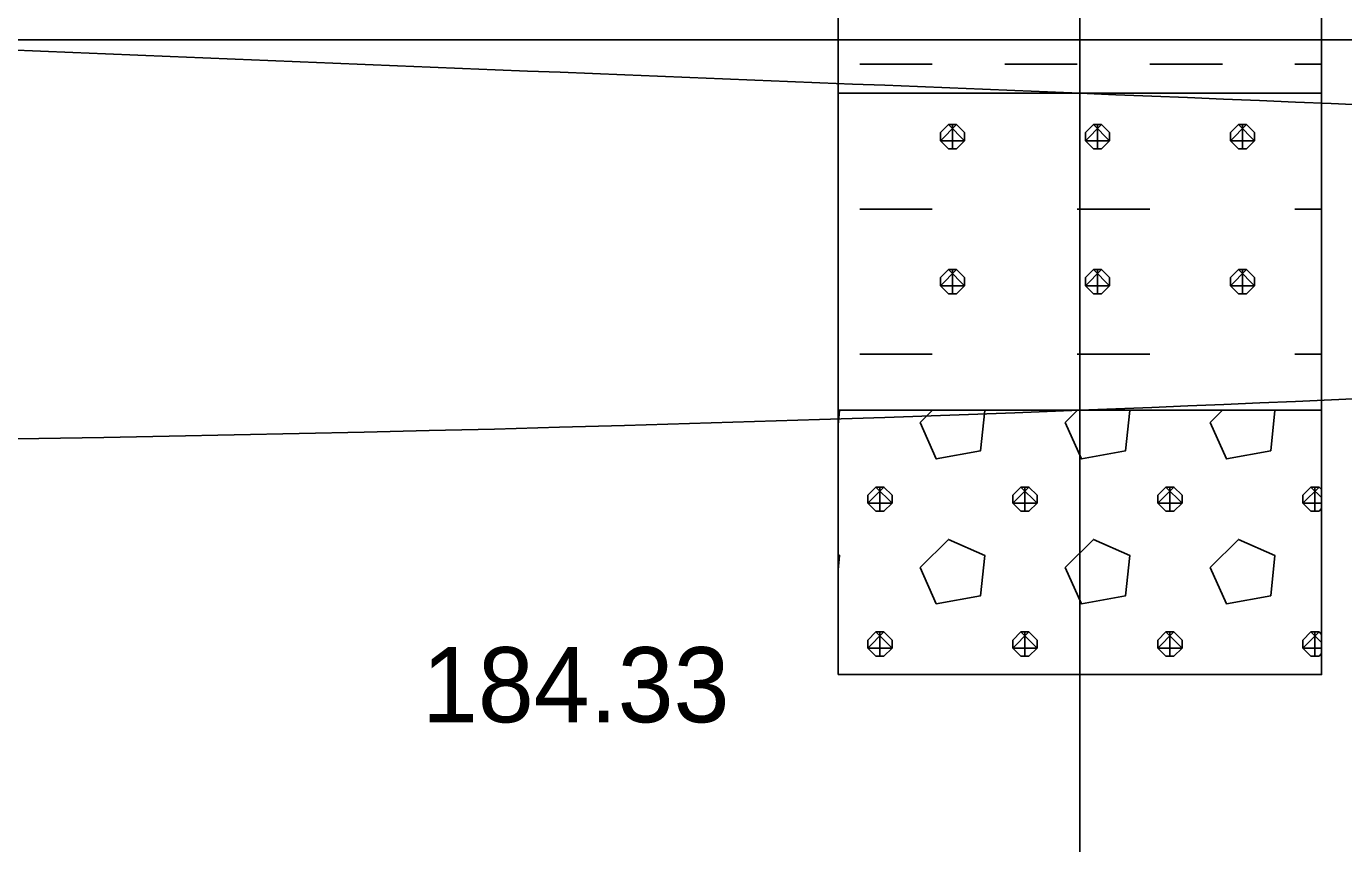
# Model space of a CAD drawing. Extents: x 3042 to 4120, y 576 to 2694.
# Drawn here: x 3421.37 to 3433.83, y 879.91 to 887.64 of the extents above; entities that cross this region are included whole.
import ezdxf

# ---------------------------------------------------------------- set-up
doc = ezdxf.new("R2010")
doc.units = 0
for name, color, linetype in [('17', 7, 'Continuous'), ('18', 7, 'Continuous'), ('51', 7, 'Continuous'), ('53', 7, 'Continuous'), ('56', 7, 'Continuous'), ('pomocna', 7, 'Continuous'), ('rozhraní', 7, 'Continuous')]:
    doc.layers.add(name, color=color, linetype=linetype)

msp = doc.modelspace()

# ---------------------------------------------------------------- linework, layer by layer
at = {"layer": '18'}
for p, q in [((3431.3317167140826, 869.8590620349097), (3431.3317167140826, 916.5090620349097)), ((3431.3317167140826, 881.8900620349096), (3431.3317167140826, 881.1280620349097)), ((3430.950716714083, 881.5090620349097), (3431.712716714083, 881.5090620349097))]:
    msp.add_line(p, q, dxfattribs=at)
at = {"layer": '51'}
for points in [[(3429.045716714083, 887.0090620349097), (3433.6177167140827, 887.0090620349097), (3433.6177167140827, 901.5090620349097), (3429.045716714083, 901.5090620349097)], [(3429.045716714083, 884.0090620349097), (3433.6177167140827, 884.0090620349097), (3433.6177167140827, 887.0090620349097), (3429.045716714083, 887.0090620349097)], [(3429.045716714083, 881.5090620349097), (3433.6177167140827, 881.5090620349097), (3433.6177167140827, 884.0090620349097), (3429.045716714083, 884.0090620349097)]]:
    msp.add_lwpolyline(points, close=True, dxfattribs=at)
for points in [[(3429.2499167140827, 887.2835620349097), (3429.935716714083, 887.2835620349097)], [(3430.6215167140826, 887.2835620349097), (3431.307316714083, 887.2835620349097)], [(3431.993116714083, 887.2835620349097), (3432.678916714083, 887.2835620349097)], [(3433.364716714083, 887.2835620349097), (3433.6177167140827, 887.2835620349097)], [(3430.088116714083, 886.7120620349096), (3430.011916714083, 886.6358620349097), (3430.011916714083, 886.5596620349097), (3430.088116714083, 886.4834620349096), (3430.164316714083, 886.4834620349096), (3430.240516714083, 886.5596620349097), (3430.240516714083, 886.6358620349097), (3430.164316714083, 886.7120620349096), (3430.088116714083, 886.7120620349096), (3430.240516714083, 886.5596620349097), (3430.011916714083, 886.5596620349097), (3430.164316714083, 886.7120620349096)], [(3430.1262167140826, 886.4834620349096), (3430.1262167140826, 886.7120620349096)], [(3431.459716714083, 886.7120620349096), (3431.383516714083, 886.6358620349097), (3431.383516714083, 886.5596620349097), (3431.459716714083, 886.4834620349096), (3431.5359167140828, 886.4834620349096), (3431.6121167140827, 886.5596620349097), (3431.6121167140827, 886.6358620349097), (3431.5359167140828, 886.7120620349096), (3431.459716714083, 886.7120620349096), (3431.6121167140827, 886.5596620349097), (3431.383516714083, 886.5596620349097), (3431.5359167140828, 886.7120620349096)], [(3431.497816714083, 886.4834620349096), (3431.497816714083, 886.7120620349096)], [(3432.8313167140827, 886.7120620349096), (3432.7551167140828, 886.6358620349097), (3432.7551167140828, 886.5596620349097), (3432.8313167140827, 886.4834620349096), (3432.9075167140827, 886.4834620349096), (3432.9837167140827, 886.5596620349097), (3432.9837167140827, 886.6358620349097), (3432.9075167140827, 886.7120620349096), (3432.8313167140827, 886.7120620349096), (3432.9837167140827, 886.5596620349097), (3432.7551167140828, 886.5596620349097), (3432.9075167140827, 886.7120620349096)], [(3432.869416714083, 886.4834620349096), (3432.869416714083, 886.7120620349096)], [(3429.2499167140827, 885.9119620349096), (3429.935716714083, 885.9119620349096)], [(3431.307316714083, 885.9119620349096), (3431.993116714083, 885.9119620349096)], [(3433.364716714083, 885.9119620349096), (3433.6177167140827, 885.9119620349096)], [(3430.088116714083, 885.3404620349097), (3430.011916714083, 885.2642620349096), (3430.011916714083, 885.1880620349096), (3430.088116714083, 885.1118620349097), (3430.164316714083, 885.1118620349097), (3430.240516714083, 885.1880620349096), (3430.240516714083, 885.2642620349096), (3430.164316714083, 885.3404620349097), (3430.088116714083, 885.3404620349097), (3430.240516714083, 885.1880620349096), (3430.011916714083, 885.1880620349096), (3430.164316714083, 885.3404620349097)], [(3430.1262167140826, 885.1118620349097), (3430.1262167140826, 885.3404620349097)], [(3431.459716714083, 885.3404620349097), (3431.383516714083, 885.2642620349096), (3431.383516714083, 885.1880620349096), (3431.459716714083, 885.1118620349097), (3431.5359167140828, 885.1118620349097), (3431.6121167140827, 885.1880620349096), (3431.6121167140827, 885.2642620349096), (3431.5359167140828, 885.3404620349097), (3431.459716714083, 885.3404620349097), (3431.6121167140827, 885.1880620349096), (3431.383516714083, 885.1880620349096), (3431.5359167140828, 885.3404620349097)], [(3431.497816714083, 885.1118620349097), (3431.497816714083, 885.3404620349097)], [(3432.8313167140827, 885.3404620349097), (3432.7551167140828, 885.2642620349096), (3432.7551167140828, 885.1880620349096), (3432.8313167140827, 885.1118620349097), (3432.9075167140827, 885.1118620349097), (3432.9837167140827, 885.1880620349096), (3432.9837167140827, 885.2642620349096), (3432.9075167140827, 885.3404620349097), (3432.8313167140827, 885.3404620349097), (3432.9837167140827, 885.1880620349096), (3432.7551167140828, 885.1880620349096), (3432.9075167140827, 885.3404620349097)], [(3432.869416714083, 885.1118620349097), (3432.869416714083, 885.3404620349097)], [(3429.2499167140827, 884.5403620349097), (3429.935716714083, 884.5403620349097)], [(3431.307316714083, 884.5403620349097), (3431.993116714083, 884.5403620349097)], [(3433.364716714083, 884.5403620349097), (3433.6177167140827, 884.5403620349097)], [(3429.045716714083, 883.8699620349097), (3429.059416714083, 884.0069620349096), (3429.054666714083, 884.0090620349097)], [(3429.8214167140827, 883.8926620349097), (3429.9738167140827, 883.5497620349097), (3430.3929167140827, 883.6259620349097), (3430.431016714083, 884.0069620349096), (3430.426266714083, 884.0090620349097)], [(3429.9378167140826, 884.0090620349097), (3429.8214167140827, 883.8926620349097)], [(3431.1930167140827, 883.8926620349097), (3431.3454167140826, 883.5497620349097), (3431.7645167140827, 883.6259620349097), (3431.802616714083, 884.0069620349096), (3431.797866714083, 884.0090620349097)], [(3431.309416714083, 884.0090620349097), (3431.1930167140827, 883.8926620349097)], [(3432.5646167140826, 883.8926620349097), (3432.717016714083, 883.5497620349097), (3433.1361167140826, 883.6259620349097), (3433.174216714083, 884.0069620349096), (3433.169466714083, 884.0090620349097)], [(3432.681016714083, 884.0090620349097), (3432.5646167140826, 883.8926620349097)], [(3429.4023167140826, 883.2830620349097), (3429.3261167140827, 883.2068620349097), (3429.3261167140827, 883.1306620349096), (3429.4023167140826, 883.0544620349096), (3429.4785167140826, 883.0544620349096), (3429.554716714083, 883.1306620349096), (3429.554716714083, 883.2068620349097), (3429.4785167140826, 883.2830620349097), (3429.4023167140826, 883.2830620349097), (3429.554716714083, 883.1306620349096), (3429.3261167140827, 883.1306620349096), (3429.4785167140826, 883.2830620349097)], [(3429.440416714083, 883.0544620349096), (3429.440416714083, 883.2830620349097)], [(3430.773916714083, 883.2830620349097), (3430.6977167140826, 883.2068620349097), (3430.6977167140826, 883.1306620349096), (3430.773916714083, 883.0544620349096), (3430.850116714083, 883.0544620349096), (3430.926316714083, 883.1306620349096), (3430.926316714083, 883.2068620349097), (3430.850116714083, 883.2830620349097), (3430.773916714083, 883.2830620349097), (3430.926316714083, 883.1306620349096), (3430.6977167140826, 883.1306620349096), (3430.850116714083, 883.2830620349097)], [(3430.812016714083, 883.0544620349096), (3430.812016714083, 883.2830620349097)], [(3432.145516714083, 883.2830620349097), (3432.069316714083, 883.2068620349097), (3432.069316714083, 883.1306620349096), (3432.145516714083, 883.0544620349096), (3432.221716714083, 883.0544620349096), (3432.297916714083, 883.1306620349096), (3432.297916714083, 883.2068620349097), (3432.221716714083, 883.2830620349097), (3432.145516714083, 883.2830620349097), (3432.297916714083, 883.1306620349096), (3432.069316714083, 883.1306620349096), (3432.221716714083, 883.2830620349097)], [(3432.1836167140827, 883.0544620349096), (3432.1836167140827, 883.2830620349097)], [(3433.517116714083, 883.2830620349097), (3433.440916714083, 883.2068620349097), (3433.440916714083, 883.1306620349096), (3433.517116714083, 883.0544620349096), (3433.593316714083, 883.0544620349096), (3433.6177167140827, 883.0788620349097)], [(3433.6177167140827, 883.1306620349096), (3433.440916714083, 883.1306620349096), (3433.593316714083, 883.2830620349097)], [(3433.6177167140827, 883.2586620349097), (3433.593316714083, 883.2830620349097), (3433.517116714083, 883.2830620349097), (3433.6177167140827, 883.1824620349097)], [(3433.5552167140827, 883.0544620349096), (3433.5552167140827, 883.2830620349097)], [(3429.8214167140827, 882.5210620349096), (3429.9738167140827, 882.1781620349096), (3430.3929167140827, 882.2543620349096), (3430.431016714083, 882.6353620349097), (3430.088116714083, 882.7877620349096), (3429.8214167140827, 882.5210620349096)], [(3431.1930167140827, 882.5210620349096), (3431.3454167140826, 882.1781620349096), (3431.7645167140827, 882.2543620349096), (3431.802616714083, 882.6353620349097), (3431.459716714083, 882.7877620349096), (3431.1930167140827, 882.5210620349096)], [(3432.5646167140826, 882.5210620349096), (3432.717016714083, 882.1781620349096), (3433.1361167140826, 882.2543620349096), (3433.174216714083, 882.6353620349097), (3432.8313167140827, 882.7877620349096), (3432.5646167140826, 882.5210620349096)], [(3429.045716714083, 882.4983620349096), (3429.059416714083, 882.6353620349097), (3429.045716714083, 882.6414620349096)], [(3429.4023167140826, 881.9114620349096), (3429.3261167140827, 881.8352620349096), (3429.3261167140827, 881.7590620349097), (3429.4023167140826, 881.6828620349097), (3429.4785167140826, 881.6828620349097), (3429.554716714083, 881.7590620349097), (3429.554716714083, 881.8352620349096), (3429.4785167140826, 881.9114620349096), (3429.4023167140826, 881.9114620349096), (3429.554716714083, 881.7590620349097), (3429.3261167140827, 881.7590620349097), (3429.4785167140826, 881.9114620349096)], [(3429.440416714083, 881.6828620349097), (3429.440416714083, 881.9114620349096)], [(3430.773916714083, 881.9114620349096), (3430.6977167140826, 881.8352620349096), (3430.6977167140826, 881.7590620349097), (3430.773916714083, 881.6828620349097), (3430.850116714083, 881.6828620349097), (3430.926316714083, 881.7590620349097), (3430.926316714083, 881.8352620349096), (3430.850116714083, 881.9114620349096), (3430.773916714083, 881.9114620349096), (3430.926316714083, 881.7590620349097), (3430.6977167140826, 881.7590620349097), (3430.850116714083, 881.9114620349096)], [(3430.812016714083, 881.6828620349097), (3430.812016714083, 881.9114620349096)], [(3432.145516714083, 881.9114620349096), (3432.069316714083, 881.8352620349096), (3432.069316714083, 881.7590620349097), (3432.145516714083, 881.6828620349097), (3432.221716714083, 881.6828620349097), (3432.297916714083, 881.7590620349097), (3432.297916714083, 881.8352620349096), (3432.221716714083, 881.9114620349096), (3432.145516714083, 881.9114620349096), (3432.297916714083, 881.7590620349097), (3432.069316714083, 881.7590620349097), (3432.221716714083, 881.9114620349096)], [(3432.1836167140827, 881.6828620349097), (3432.1836167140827, 881.9114620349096)], [(3433.517116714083, 881.9114620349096), (3433.440916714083, 881.8352620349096), (3433.440916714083, 881.7590620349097), (3433.517116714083, 881.6828620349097), (3433.593316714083, 881.6828620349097), (3433.6177167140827, 881.7072620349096)], [(3433.6177167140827, 881.7590620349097), (3433.440916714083, 881.7590620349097), (3433.593316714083, 881.9114620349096)], [(3433.6177167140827, 881.8870620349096), (3433.593316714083, 881.9114620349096), (3433.517116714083, 881.9114620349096), (3433.6177167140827, 881.8108620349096)], [(3433.5552167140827, 881.6828620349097), (3433.5552167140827, 881.9114620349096)]]:
    msp.add_lwpolyline(points, dxfattribs=at)
at = {"layer": '53'}
for points in [[(3429.045716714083, 916.5090620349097), (3429.045716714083, 881.5090620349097)], [(3433.6177167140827, 916.5090620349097), (3433.6177167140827, 881.5090620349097)], [(3429.045716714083, 887.0090620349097), (3433.6177167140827, 887.0090620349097)], [(3429.045716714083, 884.0090620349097), (3433.6177167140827, 884.0090620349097)], [(3429.045716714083, 881.5090620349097), (3433.6177167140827, 881.5090620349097)]]:
    msp.add_lwpolyline(points, dxfattribs=at)
at = {"layer": '56'}
for points in [[(3431.3317167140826, 887.3900620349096), (3431.3317167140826, 886.6280620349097)], [(3430.950716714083, 887.0090620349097), (3431.712716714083, 887.0090620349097)], [(3431.3317167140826, 884.3900620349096), (3431.3317167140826, 883.6280620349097)], [(3430.950716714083, 884.0090620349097), (3431.712716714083, 884.0090620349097)], [(3431.3317167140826, 881.8900620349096), (3431.3317167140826, 881.1280620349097)], [(3430.950716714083, 881.5090620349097), (3431.712716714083, 881.5090620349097)]]:
    msp.add_lwpolyline(points, dxfattribs=at)
at = {"layer": 'pomocna'}
msp.add_line((3431.3317167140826, 864.8590620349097), (3431.3317167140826, 917.8590620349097), dxfattribs=at)
at = {"layer": 'rozhraní'}
for points in [[(3248.313660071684, 891.8591120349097), (3256.3217167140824, 891.8591120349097), (3352.5717167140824, 886.4090620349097), (3431.331691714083, 884.0090620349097), (3453.0617167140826, 885.4090620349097), (3491.5217167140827, 887.3591120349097), (3557.3317167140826, 884.6590620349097), (3580.051716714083, 895.0090120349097), (3619.0817167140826, 891.2590620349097), (3629.2745825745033, 891.2590620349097)], [(3327.731251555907, 891.6486311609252), (3352.6357167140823, 891.4090620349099), (3372.3327436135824, 890.6912689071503), (3392.0153061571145, 889.3178217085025), (3411.682073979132, 887.8899946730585), (3431.3317167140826, 887.0090620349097), (3453.0617167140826, 886.9090620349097), (3491.5217167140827, 891.3591120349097), (3507.9473907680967, 889.8031245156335), (3524.476644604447, 888.6483564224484), (3540.9809344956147, 888.0489536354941), (3549.183548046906, 888.005684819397), (3553.26544223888, 888.0565884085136), (3557.3317167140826, 888.1590620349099), (3567.4684942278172, 889.0537677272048)], [(3518.8092174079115, 887.5130386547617), (3431.6794431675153, 887.5130386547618), (3407.745558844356, 887.5130386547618)], [(3311.776722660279, 872.8264542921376), (3352.5717167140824, 872.4090620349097), (3453.0617167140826, 876.9090620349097), (3491.5217167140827, 872.8591120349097), (3557.3317167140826, 880.1590620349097), (3580.051716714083, 879.0090120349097), (3619.0817167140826, 872.7591120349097), (3628.716834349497, 873.2727391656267)]]:
    msp.add_spline(points, degree=3, dxfattribs=at)

# ---------------------------------------------------------------- texts
at = {"layer": '17'}
msp.add_text('184.33', height=0.7112000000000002, dxfattribs=at).set_placement((3425.1087167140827, 881.0569620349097))

doc.saveas('drawing.dxf')
